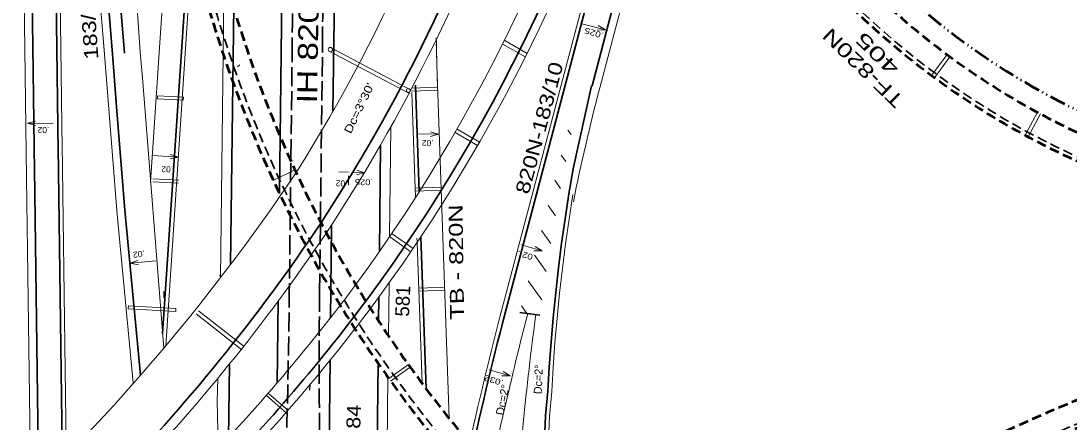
# Model space of a CAD drawing. Extents: x 2354993 to 2372084, y 6966390 to 6990057.
# Drawn here: x 2364227 to 2365274, y 6978118 to 6978519 of the extents above; entities that cross this region are included whole.
import ezdxf

# ---------------------------------------------------------------- set-up
doc = ezdxf.new("R2010")
doc.units = 0
doc.header["$LTSCALE"] = 3.2
for name, pattern in [('DASH_DOUBLE_DOT', [9.2, 5, -1.2, 0.3, -1.2, 0.3, -1.2]), ('LONG_DASHED', [7.5, 6, -1.5]), ('MEDIUM_DASHED', [4.5, 3, -1.5])]:
    doc.linetypes.add(name, pattern=pattern)
for name, color, linetype, lineweight in [('11', 7, 'Continuous', 13), ('12', 7, 'Continuous', 13), ('13', 7, 'Continuous', 13), ('17', 7, 'Continuous', 13), ('19', 7, 'Continuous', 13), ('2', 7, 'Continuous', 35), ('30', 7, 'Continuous', 13), ('4', 7, 'Continuous', 13), ('5', 7, 'Continuous', 35), ('59', 7, 'Continuous', 25), ('6', 7, 'Continuous', 35), ('60', 7, 'DASH_DOUBLE_DOT', 53), ('61', 7, 'Continuous', 13), ('7', 7, 'Continuous', 13)]:
    doc.layers.add(name, color=color, linetype=linetype, lineweight=lineweight)

msp = doc.modelspace()

# ---------------------------------------------------------------- linework, layer by layer
at = {"layer": '12'}
for p, q in [((2364229.452, 6978568.704), (2364232.173, 6978361.901)), ((2364710.073, 6978498.868), (2364732.351, 6978486.078)), ((2364534.549, 6978488.225), (2364614.793, 6978445.961)), ((2364535.309, 6978492.345), (2364616.657, 6978449.5)), ((2364708.082, 6978495.399), (2364730.36, 6978482.609)), ((2364314.268, 6978430.633), (2364309.968, 6978484.875)), ((2364445.177, 6978474.693), (2364443.065, 6978472.563)), ((2364642.983, 6978452.418), (2364616.998, 6978451.499)), ((2364643.114, 6978449.419), (2364617.13, 6978448.502)), ((2364388.851, 6978439.288), (2364362.893, 6978440.747)), ((2364389.019, 6978442.283), (2364388.851, 6978439.288)), ((2364660.463, 6978407.102), (2364682.84, 6978393.967)), ((2364662.488, 6978410.551), (2364684.865, 6978397.416)), ((2364618.872, 6978398.533), (2364618.766, 6978401.531)), ((2364384.356, 6978359.299), (2364358.398, 6978360.757)), ((2364384.189, 6978356.304), (2364358.231, 6978357.762)), ((2364646.517, 6978352.48), (2364620.532, 6978351.561)), ((2364646.641, 6978349.481), (2364620.657, 6978348.564)), ((2364595.4, 6978302.62), (2364616.13, 6978287.862)), ((2364597.72, 6978305.879), (2364618.45, 6978291.12)), ((2364622.406, 6978298.595), (2364622.3, 6978301.593)), ((2364650.051, 6978252.542), (2364624.066, 6978251.623)), ((2364650.168, 6978249.543), (2364624.184, 6978248.626)), ((2364334.007, 6978233.889), (2364333.84, 6978230.894)), ((2364381.236, 6978228.23), (2364333.84, 6978230.894)), ((2364381.403, 6978231.225), (2364334.007, 6978233.889)), ((2364381.403, 6978231.225), (2364381.236, 6978228.23)), ((2364401.638, 6978225.773), (2364447.213, 6978189.9)), ((2364404.112, 6978228.916), (2364449.687, 6978193.043)), ((2364625.834, 6978201.655), (2364625.94, 6978198.657))]:
    msp.add_line(p, q, dxfattribs=at)
msp.add_lwpolyline([(2364389.019, 6978442.283), (2364363.061, 6978443.742), (2364362.893, 6978440.747)], dxfattribs=at)
for centre, radius in [((2364535.877, 6978489.877), 2.162), ((2364613.685, 6978448.959), 1.938)]:
    msp.add_circle(centre, radius, dxfattribs=at)
at = {"layer": '19'}
for p, q in [((2364810.814, 6978509.763), (2364802.508, 6978509.456)), ((2364233.097, 6978416.421), (2364241.133, 6978418.549)), ((2364643.882, 6978405.298), (2364635.855, 6978403.138)), ((2364383.93, 6978382.36), (2364375.805, 6978380.608)), ((2364747.593, 6978288.913), (2364739.28, 6978288.905)), ((2364335.857, 6978276.331), (2364343.614, 6978279.319)), ((2364715.597, 6978163.89), (2364707.284, 6978163.882))]:
    msp.add_line(p, q, dxfattribs=at)
at = {"layer": '19', "linetype": 'MEDIUM_DASHED'}
for p, q in [((2364553.948, 6978363.903), (2364553.909, 6978353.058)), ((2364570.118, 6978366.76), (2364562.037, 6978364.816))]:
    msp.add_line(p, q, dxfattribs=at)
at = {"layer": '19'}
for points in [[(2364785.774, 6978515.909), (2364810.814, 6978509.763), (2364803.598, 6978513.878)], [(2364258.876, 6978415.937), (2364233.097, 6978416.421), (2364241.041, 6978413.996)], [(2364621.96, 6978405.618), (2364643.882, 6978405.298), (2364635.927, 6978407.69)], [(2364358.202, 6978384.04), (2364383.93, 6978382.36), (2364376.107, 6978385.151)], [(2364726.501, 6978294.896), (2364747.593, 6978288.913), (2364740.528, 6978293.283)], [(2364361.536, 6978278.65), (2364335.857, 6978276.331), (2364344.017, 6978274.783)], [(2364694.505, 6978169.873), (2364715.597, 6978163.89), (2364708.532, 6978168.26)]]:
    msp.add_lwpolyline(points, dxfattribs=at)
at = {"layer": '19', "linetype": 'MEDIUM_DASHED'}
msp.add_lwpolyline([(2364544.358, 6978367.832), (2364570.118, 6978366.76), (2364562.232, 6978369.365)], dxfattribs=at)
at = {"layer": '2'}
for p, q in [((2364368.17, 6978206.229), (2364399.023, 6978669.972)), ((2364307.528, 6978616.887), (2364317.943, 6978485.507)), ((2364319.49, 6978617.835), (2364329.905, 6978486.455)), ((2364484.961, 6978346.199), (2364488.209, 6978621.342)), ((2364538.433, 6978428.325), (2364539.995, 6978560.576)), ((2364321.764, 6978437.311), (2364317.943, 6978485.507)), ((2364330.314, 6978329.457), (2364321.473, 6978440.986)), ((2364584.781, 6978288.034), (2364586.041, 6978394.75)), ((2364330.314, 6978329.457), (2364346.159, 6978164.504)), ((2364482.725, 6978156.923), (2364483.686, 6978238.319)), ((2364583.963, 6978218.733), (2364584.244, 6978242.506)), ((2364535.5, 6978179.675), (2364533.978, 6978050.938)), ((2364581.463, 6978007.018), (2364583.464, 6978176.442))]:
    msp.add_line(p, q, dxfattribs=at)
msp.add_lwpolyline([(2364537.098, 6978314.898), (2364536.33, 6978249.932), (2364536, 6978222.017)], dxfattribs=at)
at = {"layer": '2', "linetype": 'LONG_DASHED'}
msp.add_arc((2367534.289, 6978489.569), 3006.329, 158.51286, 179.87539, dxfattribs=at)
at = {"layer": '30'}
msp.add_line((2364369.278, 6978241.689), (2364369.359, 6978248.572), dxfattribs=at)
at = {"layer": '4'}
for p, q in [((2364299.557, 6978616.203), (2364309.968, 6978484.875)), ((2364594.957, 6978302.811), (2364596.255, 6978412.759)), ((2364593.789, 6978203.885), (2364594.411, 6978256.582)), ((2364591.974, 6978050.253), (2364593.298, 6978162.457))]:
    msp.add_line(p, q, dxfattribs=at)
msp.add_arc((2367605.673, 6978746.13), 3270.045, 157.44674, 184.53246, dxfattribs=at)
at = {"layer": '5'}
for p, q in [((2364797.288, 6978453.72), (2364856.416, 6978677.989)), ((2364707.829, 6978216.381), (2364807.115, 6978592.979)), ((2364263.839, 6978387.483), (2364261.27, 6978582.702)), ((2364240.093, 6978368.193), (2364237.452, 6978568.809)), ((2364436.064, 6978275.086), (2364439.162, 6978533.446)), ((2364624.662, 6978348.013), (2364620.895, 6978454.534)), ((2364267.888, 6978079.876), (2364263.771, 6978392.69)), ((2364631.637, 6978150.774), (2364626.262, 6978302.759)), ((2364745.09, 6978224.447), (2364725.284, 6978227.231)), ((2364433.986, 6978101.712), (2364434.867, 6978175.192))]:
    msp.add_line(p, q, dxfattribs=at)
at = {"layer": '5', "lineweight": 13}
for p, q in [((2364805.021, 6978451.673), (2364864.153, 6978675.957)), ((2364356.183, 6978357.451), (2364377.072, 6978671.432)), ((2364371.359, 6978193.923), (2364398.813, 6978606.559)), ((2364703.961, 6978217.401), (2364803.248, 6978593.999)), ((2364267.797, 6978390.761), (2364265.27, 6978582.755)), ((2364425.903, 6978261.761), (2364429.49, 6978566.1)), ((2364347.958, 6978461.222), (2364345.856, 6978487.735)), ((2364369.336, 6978191.519), (2364347.579, 6978465.988)), ((2364654.697, 6978121.177), (2364642.881, 6978455.312)), ((2364620.869, 6978342.06), (2364617.157, 6978447.031)), ((2364322.328, 6978328.965), (2364313.602, 6978439.055)), ((2364773.207, 6978409.446), (2364776.385, 6978405.016)), ((2364271.836, 6978083.919), (2364267.734, 6978395.661)), ((2364766.591, 6978384.353), (2364770.987, 6978378.224)), ((2364236.303, 6978048.324), (2364232.175, 6978361.911)), ((2364759.976, 6978359.259), (2364765.799, 6978351.14)), ((2364774.327, 6978320.294), (2364778.131, 6978344.982)), ((2364322.351, 6978328.693), (2364338.849, 6978156.952)), ((2364753.36, 6978334.166), (2364760.827, 6978323.754)), ((2364770.905, 6978295.883), (2364774.335, 6978320.348)), ((2364746.745, 6978309.072), (2364756.078, 6978296.057)), ((2364627.435, 6978156.378), (2364622.46, 6978297.071)), ((2364724.995, 6978288.444), (2364724.259, 6978288.151)), ((2364767.753, 6978271.136), (2364770.911, 6978295.933)), ((2364740.129, 6978283.979), (2364751.558, 6978268.041)), ((2364764.959, 6978246.559), (2364767.759, 6978271.19)), ((2364733.513, 6978258.885), (2364747.275, 6978239.696)), ((2364762.413, 6978221.397), (2364764.964, 6978246.609)), ((2364726.898, 6978233.792), (2364732.311, 6978226.243)), ((2364729.102, 6978210.773), (2364733.15, 6978226.125)), ((2364760.301, 6978197.005), (2364762.419, 6978221.455)), ((2364758.47, 6978172.248), (2364760.305, 6978197.055)), ((2364757.039, 6978148.259), (2364758.473, 6978172.305)), ((2364754.859, 6978123.602), (2364757.03, 6978148.145)), ((2364423.845, 6978091.472), (2364422.744, 6978138.5)), ((2364753.829, 6978098.812), (2364754.871, 6978123.787))]:
    msp.add_line(p, q, dxfattribs=at)
at = {"layer": '5', "linetype": 'LONG_DASHED'}
for p, q in [((2364497.721, 6978496.465), (2364494.781, 6978247.382)), ((2364525.028, 6978247.025), (2364527.968, 6978496.107))]:
    msp.add_line(p, q, dxfattribs=at)
at = {"layer": '5'}
msp.add_lwpolyline([(2364748.237, 6978049.03), (2364748.453, 6978074.017), (2364749.833, 6978098.979), (2364750.875, 6978123.954), (2364753.046, 6978148.498), (2364754.481, 6978172.543), (2364756.316, 6978197.35), (2364758.434, 6978221.8), (2364760.985, 6978247.011), (2364763.785, 6978271.641), (2364766.943, 6978296.439), (2364770.374, 6978320.903), (2364774.178, 6978345.591), (2364778.407, 6978370.695), (2364796.946, 6978453.796)], dxfattribs=at)
at = {"layer": '5', "linetype": 'MEDIUM_DASHED', "lineweight": 53}
for centre, radius, start, end in [((2365591.415, 6978874.774), 1226.227, 157.96139, 222.27477), ((2365591.415, 6978874.774), 1202.227, 157.96139, 223.28034), ((2365602.828, 6979091.775), 755.944, 184.10697, 276.23324), ((2365602.828, 6979091.775), 781.944, 185.55228, 276.23324), ((2365952.337, 6976500.333), 1770.947, 100.46125, 118.99651), ((2365952.338, 6976500.332), 1744.947, 99.58224, 117.42976)]:
    msp.add_arc(centre, radius, start, end, dxfattribs=at)
at = {"layer": '5', "linetype": 'MEDIUM_DASHED'}
for centre, radius, start, end in [((2365591.415, 6978874.774), 1220.227, 157.96139, 222.48424), ((2365602.828, 6979091.775), 777.944, 184.10654, 276.23324), ((2365952.338, 6976500.332), 1748.947, 99.58224, 117.67913)]:
    msp.add_arc(centre, radius, start, end, dxfattribs=at)
at = {"layer": '5', "linetype": 'LONG_DASHED'}
for centre, radius, start, end in [((2367702.294, 6978491.735), 3204.576, 168.65748, 179.91543), ((2355201.239, 6978357.07), 9294.189, 357.45391, 359.3238), ((2370414.262, 6978177.512), 5889.645, 179.32374, 181.73104)]:
    msp.add_arc(centre, radius, start, end, dxfattribs=at)
at = {"layer": '5', "lineweight": 13}
for centre, radius, start, end in [((2363217.727, 6979240.251), 1666, 323.74727, 347.27016), ((2363127.192, 6979233.99), 1625.022, 327.75883, 346.05765), ((2363217.727, 6979240.251), 1692, 323.39108, 343.06808), ((2363127.192, 6979233.99), 1683.022, 326.53499, 342.55536), ((2367633.012, 6978561.052), 2992, 181.13725, 182.02529), ((2367632.915, 6978563.806), 2992, 181.31084, 182.02528), ((2366632.436, 6977969.881), 1889.859, 165.23027, 168.77793), ((2362823.255, 6979494.499), 2021.91, 312.68984, 326.1095), ((2363008.703, 6979329.968), 1834.853, 315.90902, 326.07506), ((2363083.622, 6979356.349), 1842.854, 314.93085, 323.30202), ((2363244.672, 6976597.082), 1645.014, 38.12295, 103.3303), ((2363062.003, 6979373.816), 1896.709, 315.80261, 322.95759), ((2368298.716, 6977752.87), 3588.778, 172.43843, 175.94649), ((2363244.672, 6976597.082), 1619.014, 38.12295, 103.3303), ((2368172.363, 6977322.346), 3582.03, 165.52996, 167.99765), ((2368799.967, 6977188.312), 4197.305, 165.90092, 168.75683)]:
    msp.add_arc(centre, radius, start, end, dxfattribs=at)
at = {"layer": '5'}
for centre, radius, start, end in [((2363217.727, 6979240.251), 1684, 323.49687, 346.83945), ((2363127.192, 6979233.99), 1673.022, 326.75894, 342.55536), ((2363014.544, 6979325.529), 1817.476, 315.51277, 326.29202), ((2363069.263, 6979367.953), 1879.359, 315.5386, 323.05986), ((2363244.672, 6976597.082), 1623.014, 38.12295, 103.3303), ((2368154.706, 6977326.865), 3559.803, 165.52972, 168.05788)]:
    msp.add_arc(centre, radius, start, end, dxfattribs=at)
at = {"layer": '59'}
msp.add_line((2364515.415, 6978149.616), (2364515.511, 6978155.73), dxfattribs=at)
at = {"layer": '6'}
for p, q in [((2364244.21, 6978056.977), (2364240.055, 6978371.067)), ((2364344.497, 6978181.803), (2364346.147, 6978164.63))]:
    msp.add_line(p, q, dxfattribs=at)
at = {"layer": '60'}
msp.add_arc((2365602.828, 6979091.775), 735.944, 200.58365, 276.23324, dxfattribs=at)
at = {"layer": '61'}
for p, q in [((2365152.147, 6978484.856), (2365136.748, 6978463.917)), ((2365154.967, 6978482.783), (2365139.563, 6978461.837)), ((2365242.476, 6978427.238), (2365230.191, 6978404.332)), ((2365245.56, 6978425.584), (2365233.272, 6978402.671)), ((2364500.375, 6978369.6), (2364478.723, 6978359.245)), ((2364425.499, 6978264.579), (2364425.478, 6978263.601)), ((2364613.809, 6978175.035), (2364594.298, 6978161.06)), ((2364615.563, 6978172.601), (2364596.051, 6978158.625)), ((2364423.242, 6978161.309), (2364422.744, 6978138.5)), ((2364491.769, 6978126.838), (2364472.005, 6978144.049)), ((2364493.74, 6978129.1), (2364473.975, 6978146.311))]:
    msp.add_line(p, q, dxfattribs=at)

# ---------------------------------------------------------------- texts
at = {"layer": '11'}
for s, rotation, width, p in [('.02', 178.117, 1.05, (2364639.064, 6978399.301)), ('.02', 163.117, 1.2, (2364741.386, 6978284.368)), ('.032', 163.117, 1.25, (2364709.39, 6978159.345))]:
    msp.add_text(s, height=6, rotation=rotation, dxfattribs=dict(at, width=width)).set_placement(p)
at = {"layer": '13'}
for s, height, rotation, width, p in [('183/10-820S', 14, 93.997, 1.25, (2364304.033, 6978480.531)), ('IH 820 HOV', 20, 88.969, 1.25, (2364522.394, 6978436.044)), ('TF-820N', 14, 135.829, 1.4, (2365110.183, 6978440.585)), ('405', 14, 135.42, 1.65, (2365105.722, 6978472.517)), ('820N-183/10', 14, 75.091, 1.25, (2364733.995, 6978344.476)), ('TB - 820N ', 14, 90.783, 1.35, (2364669.499, 6978220.06)), ('4,184', 14, 88.164, 1.15, (2364564.684, 6978080.867))]:
    msp.add_text(s, height=height, rotation=rotation, dxfattribs=dict(at, width=width)).set_placement(p)
msp.add_text('581', height=14, rotation=87.418, dxfattribs=at).set_placement((2364614.417, 6978222.755))
at = {"layer": '17', "width": 1.25}
msp.add_text("Dc=3°30'", height=7.999, rotation=64.213, dxfattribs=at).set_placement((2364556.265, 6978405.152))
at = {"layer": '19'}
for s, height, rotation, width, p in [('.025', 6, 162.703, 1.25, (2364809.503, 6978506.442)), ('.02', 6, 181.098, 1.05, (2364254.894, 6978412.688)), ('.02', 6, 178.438, 1.05, (2364378.714, 6978373.137)), ('.025', 6, 179.794, 1.15, (2364578.36, 6978360.372)), ('.02', 5.999, 178.287, 1.05, (2364552.967, 6978359.03)), ('.02', 6, 187.333, 1.1, (2364350.193, 6978289.131))]:
    msp.add_text(s, height=height, rotation=rotation, dxfattribs=dict(at, width=width)).set_placement(p)
at = {"layer": '7'}
msp.add_text('Dc=2°', height=8, rotation=87.759, dxfattribs=at).set_placement((2364747.018, 6978145.42))
at = {"layer": '7', "width": 1.05}
msp.add_text('Dc=2°', height=8, rotation=78.787, dxfattribs=at).set_placement((2364708.829, 6978123.909))

doc.saveas('drawing.dxf')
